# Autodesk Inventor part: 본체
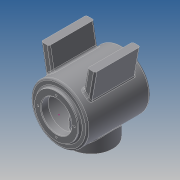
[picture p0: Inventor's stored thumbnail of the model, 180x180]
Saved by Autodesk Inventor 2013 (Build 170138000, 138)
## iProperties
Created: 2015-01
Part Number: 본체
Material: Generic
Document SubType Name: Modeling
Designer: kb54323
Density: 1 g/cm^3
Author: kb54323
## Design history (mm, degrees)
sketch "스케치1"
  geometry: C1 r 50 at (0, 0); 1 further point
  constraints: 1 centre point, 1 coincident
  dimensions: "d0" = 100 diameter of C1
extrude "돌출1" new body sketch "스케치1" distance "d2" = 112; taper "d3" = 0 deg
sketch "스케치2"
  geometry: C1 r 50 at (0, 0) reference; C2 r 38 at (0, 0)
  constraints: 1 centre point, 1 coincident
  dimensions: "d4" = 76 diameter of C2
extrude "돌출2" join sketch "스케치2" distance "d6" = 5; taper "d7" = 0 deg
node "작업 평면1"
sketch "스케치3"
  geometry: L1 (38, 117)-(-38, 117) reference; L2 (38, -5)-(-38, -5) reference; L3 (27, 117)-(27, 105); L4 (50, 112)-(-50, 112) reference; L5 (27, 105)-(45, 105); L6 (45, 105)-(45, 8); L7 (0, 117)-(0, -5); L8 (-50, 0)-(50, 0) reference; L9 (45, 8)-(27, 8); L10 (27, 8)-(27, -5); 1 further point
  constraints: 12 end point, 3 perpendicular, 2 midpoint, 2 point on line, 1 collinear, 1 parallel
  dimensions: "d8" = 54 diameter of L3 L7; "d10" = 90 diameter of L6 L7; "d75" = 7 distance between parallel lines of L5 L4; "d79" = 5 distance from line of L10.end L8 (derived); "d80" = 100 diameter of L8.end L7 (derived); "d82" = 8 distance from line of L8 L6.end
revolve "회전1" sketch "스케치3" stored, may be unused: angle "d12" = 90 deg
sketch "스케치5"
  geometry: L1 (-39.336, -30.865)-(-48, -80); L2 (-48, -80)-(-34, -80); L3 (-34, -80)-(-27.282, -41.901); A1 r 50 centre (0, 0) between (-39.336, -30.865) and (-27.282, -41.901) reference; A2 r 50 centre (0, 0) between (-39.336, -30.865) and (-27.282, -41.901); 1 further point
  constraints: 6 end point, 4 point on circle, 1 centre point, 1 coincident, 1 concentric, 1 horizontal, 1 parallel
  dimensions: "d14" = 100 deg angle of L2 L1; "d15" = 14 distance of L1.end L2.end; "d17" = 48 horizontal distance of L1.end point (0, 0); "d19" = 80 distance from line of L2 point (0, 0)
extrude "돌출3" join sketch "스케치5" stored distance "d20" = 80; taper "d21" = 0 deg
node "작업 평면3"
sketch "스케치6"
  geometry: L1 (86, -101)-(10, -101) reference; C1 r 38 at (48, -39); 1 further point
  constraints: 1 centre point, 1 vertical alignment
  dimensions: "d23" = 76 diameter of C1; "d25" = 62 distance from line of C1.centre L1
extrude "돌출4" join sketch "스케치6" stored distance "d26" = 80; taper "d27" = 0 deg
sketch "스케치7"
  geometry: C1 r 38 at (0, 0) reference; C2 r 27 at (0, 0); 1 further point
  constraints: 1 centre point, 1 coincident
  dimensions: "d28" = 54 diameter of C2
extrude "돌출5" cut sketch "스케치7" stored distance "d30" = 30; taper "d31" = 0 deg
sketch "스케치8"
  geometry: C1 r 27 at (0, 0) reference; 2 further points
  constraints: 1 vertical alignment
  dimensions: "d32" = 32 distance of C1.centre point (0, 32)
hole "구멍1" sketch "스케치8" at (0, 32) diameter "d33" = 3.242; stored, may be unused: countersink angle "d37" = 90 deg, drill point angle "d39" = 118 deg; dims "d34" = 8, "d35" = 4, "d36" = 2, "d38" = 10
node "작업 평면5"
  node "작업 평면4"
sketch "스케치11"
  geometry: L1 (30, 6)-(84, 6); L2 (84, 6)-(84, -6); L3 (84, -6)-(30, -6); L4 (30, -6)-(30, 6); L5 (-5, -38)-(-5, 38) reference; 2 further points
  constraints: 8 end point, 2 parallel, 1 horizontal, 1 horizontal alignment, 1 midpoint, 1 perpendicular
  dimensions: "d55" = 54 distance of L1.start L1.end; "d57" = 12 distance of L3.end L1.start; "d59" = 35 distance between parallel lines of L4 L5
extrude "돌출6" join sketch "스케치11" stored distance "d60" = 80; taper "d61" = 0 deg
sketch "스케치12"
  geometry: L1 (38, -5)-(-38, -5) reference; 2 further points
  constraints: 1 vertical alignment, 1 other
  dimensions: "d62" = 62 distance from line of point (0, 57) L1
feature "엠보싱1" sketch "스케치12" dims "d8" = 54, "d10" = 90, "d63" = 0.5, "d64" = 0, "d75" = 7, "d79" = 5 (derived), "d80" = 100 (derived), "d82" = 8
fillet "모깎기1" dims "d65" = 3, "d66" = 3
fillet "모깎기2" dims "d67" = 3
chamfer "모따기1" distance "d68" = 1; stored, may be unused: second distance "d69" = 2, angle "d70" = 45 deg
chamfer "모따기2" distance "d71" = 1; stored, may be unused: second distance "d72" = 2, angle "d73" = 45 deg
sketch "스케치13"
  geometry: C1 r 27 at (0, 0) reference; 1 further point
  constraints: 1 vertical alignment
  dimensions: "d83" = 32 distance of C1.centre point (0, 32)
hole "구멍3" sketch "스케치13" at (0, 32) diameter "d84" = 3.242; stored, may be unused: countersink angle "d88" = 90 deg, drill point angle "d90" = 118 deg; dims "d85" = 8, "d86" = 4, "d87" = 2, "d89" = 10
sketch "스케치14"
  geometry: C1 r 38 at (0, 0) reference; 1 further point
  constraints: 1 vertical alignment
  dimensions: "d94" = 32 distance of C1.centre point (0, 32)
hole "구멍4" sketch "스케치14" at (0, 32) diameter "d95" = 3.242; stored, may be unused: countersink angle "d99" = 90 deg, drill point angle "d101" = 118 deg; dims "d96" = 8, "d97" = 4, "d98" = 2, "d100" = 10
sketch "스케치15"
  geometry: 1 further point
node "솔리드1"
mirror "대칭1"
mirror "대칭2"
pattern_circular "원형 패턴1" dims angle "d41" = 360 deg
pattern_circular "원형 패턴3" dims angle "d92" = 360 deg
pattern_circular "원형 패턴4" dims angle "d103" = 360 deg
other parameters: "d22" = -142, "d54" = -2
